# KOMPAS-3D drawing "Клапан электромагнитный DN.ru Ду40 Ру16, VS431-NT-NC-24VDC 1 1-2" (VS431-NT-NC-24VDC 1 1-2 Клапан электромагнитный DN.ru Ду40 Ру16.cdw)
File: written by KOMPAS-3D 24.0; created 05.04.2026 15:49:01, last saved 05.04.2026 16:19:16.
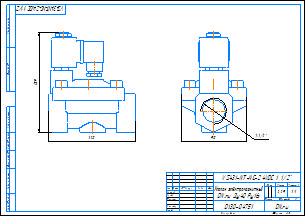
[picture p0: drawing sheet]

Document properties: c3d_UniqueCompID: ef56311e-7521-43dc-8291-0e6108b3d81d; Автор: artio; Класс точности: c; Знак неуказанной шероховатости: Шероховатость не задана; Рассекать на разрезах: Да; c3d_UniqueCompID: ef56311e-7521-43dc-8291-0e6108b3d81d; Автор: artio; Класс точности: c; Знак неуказанной шероховатости: Шероховатость не задана; Рассекать на разрезах: Да; c3d_UniqueCompID: ef56311e-7521-43dc-8291-0e6108b3d81d; Автор: artio; Класс точности: c; Знак неуказанной шероховатости: Шероховатость не задана; Рассекать на разрезах: Да; c3d_UniqueCompID: ef56311e-7521-43dc-8291-0e6108b3d81d; Автор: artio; Класс точности: c; Знак неуказанной шероховатости: Шероховатость не задана; Рассекать на разрезах: Да; Автор: artio; Форматы листов документа: A3; Полное имя файла: VS431-NT-NC-24VDC 1 1-2 Клапан электромагнитный DN.ru Ду40 Ру16.m3d; Масса: 2.285; Наименование: Клапан электромагнитный DN.ru Ду40 Ру16; Количество листов документа: 1; Примечание: D130-04751

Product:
- Body: Тело 1  | qty 1
    Масса: 3.859459
- Part/product: Клапан электромагнитный DN.ru Ду40 Ру16  | designation VS431-NT-NC-24VDC 1 1-2
    Масса: 2.285
    Раздел спецификации: Прочие изделия
    Примечание: D130-04751
    additional columns: ef56311e-7521-43dc-8291-0e6108b3d81d; artio; c; Шероховатость не задана; Да

Views: Вид 1, Спереди
Referenced files in C:\Users\artio\OneDrive\Рабочий стол\Клапан электромагнитный DN.ru\VS431\VS431-ET-NC\: VS431-ET-NC-24VDC 3-4 Клапан электромагнитный DN.ru Ду20 Ру16.m3d, VS431-ET-NC-24VDC 3-4 Клапан электромагнитный DN.ru Ду20 Ру16.cdw
Referenced files in C:\Users\artio\OneDrive\Рабочий стол\Клапан электромагнитный DN.ru\VS431\VS431-NT-NC\: VS431-NT-NC-24VDC 1 1-2 Клапан электромагнитный DN.ru Ду40 Ру16.m3d
Referenced files in C:\Users\artio\OneDrive\Рабочий стол\Клапан электромагнитный DN.ru\VS431\VS431-NT-NC\VS431-NT-NC-24VDC\Ду40\: VS431-NT-NC-24VDC 1 1-2 Клапан электромагнитный DN.ru Ду40 Ру16.m3d
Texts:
  VS431-NT-NC-24VDC 1 1-2
  Клапан электромагнитный
  DN.ru Ду40 Ру16
  VS431-NT-NC-24VDC 1 1/2"
  VS431-NT-NC-24VDC 1 1/2"-
  Клапан электромагнитный DN.ru Ду40 Ру16
  VS431-NT-NC-24VDC 1 1-2 Клапан электромагнитный DN.ru Ду40 Ру16
Dimensions and other numbers on the sheet: 0; 3; 2; 4; 90; 1 1/2"; 1:1; 1; 2,29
